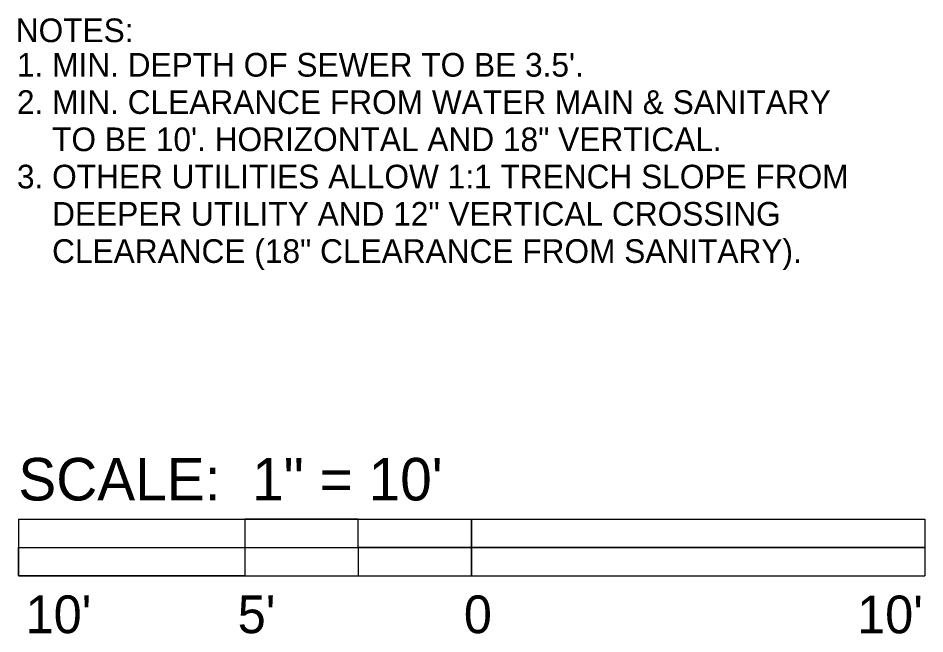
# Model space of a CAD drawing. Extents: x 27101070.6 to 27101150.6, y 1158854.7 to 1158902.9.
# Drawn here: x 27101130.61 to 27101150.61, y 1158854.72 to 1158868.3 of the extents above; entities that cross this region are included whole.
import ezdxf

# ---------------------------------------------------------------- set-up
doc = ezdxf.new("R2010")
doc.units = 0
doc.layers.add('G-ANNO-CELL', color=7, linetype='Continuous')
doc.layers.add('G-ANNO-TEXT', color=7, linetype='Continuous')

msp = doc.modelspace()

# ---------------------------------------------------------------- linework, layer by layer
at = {"layer": 'G-ANNO-CELL'}
for p, q in [((27101130.611, 1158857.247), (27101140.61, 1158857.247)), ((27101130.611, 1158857.247), (27101130.611, 1158855.997)), ((27101135.611, 1158857.247), (27101135.611, 1158855.997)), ((27101140.61, 1158857.247), (27101150.61, 1158857.247)), ((27101140.61, 1158857.247), (27101140.61, 1158855.997)), ((27101150.61, 1158857.247), (27101150.61, 1158855.997)), ((27101130.611, 1158856.622), (27101135.611, 1158856.622)), ((27101135.611, 1158856.622), (27101140.61, 1158856.622)), ((27101140.61, 1158856.622), (27101150.61, 1158856.622)), ((27101130.611, 1158855.997), (27101140.61, 1158855.997)), ((27101140.61, 1158855.997), (27101150.61, 1158855.997))]:
    msp.add_line(p, q, dxfattribs=at)
for points in [[(27101135.611, 1158856.622), (27101138.11, 1158856.622), (27101138.11, 1158857.247), (27101135.611, 1158857.247)], [(27101140.61, 1158857.247), (27101150.61, 1158857.247), (27101150.61, 1158856.622), (27101140.61, 1158856.622)], [(27101130.611, 1158856.622), (27101135.611, 1158856.622), (27101135.611, 1158855.997), (27101130.611, 1158855.997)], [(27101138.11, 1158855.997), (27101140.61, 1158855.997), (27101140.61, 1158856.622), (27101138.11, 1158856.622)]]:
    msp.add_lwpolyline(points, close=True, dxfattribs=at)

# ---------------------------------------------------------------- texts
for s, height, p in [('SCALE:  1" = 10\'', 0.93744, (27101130.611, 1158857.66)), ("10'", 0.8333, (27101130.77, 1158854.731)), ("5'", 0.8333, (27101135.45, 1158854.731)), ('0', 0.833, (27101140.439, 1158854.731)), ("10'", 0.8333, (27101149.114, 1158854.728))]:
    msp.add_text(s, height=height, dxfattribs=at).set_placement(p)
at = {"layer": 'G-ANNO-TEXT'}
for s, p in [('NOTES:', (27101130.554, 1158867.772)), ("1. MIN. DEPTH OF SEWER TO BE 3.5'.", (27101130.58, 1158867.011)), ('2. MIN. CLEARANCE FROM WATER MAIN & SANITARY', (27101130.58, 1158866.189)), ('    TO BE 10\'. HORIZONTAL AND 18" VERTICAL. ', (27101130.58, 1158865.367)), ('3. OTHER UTILITIES ALLOW 1:1 TRENCH SLOPE FROM', (27101130.58, 1158864.545)), ('    DEEPER UTILITY AND 12" VERTICAL CROSSING', (27101130.58, 1158863.723)), ('    CLEARANCE (18" CLEARANCE FROM SANITARY).', (27101130.58, 1158862.901))]:
    msp.add_text(s, height=0.522, dxfattribs=at).set_placement(p)

doc.saveas('drawing.dxf')
